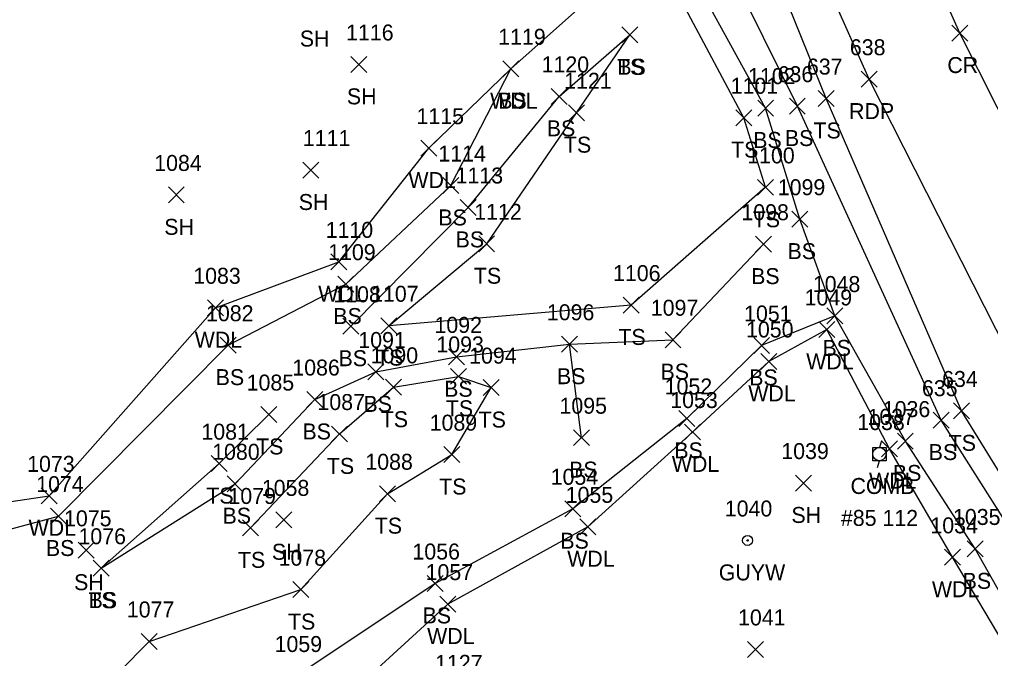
# Model space of a CAD drawing. Extents: x 1879695 to 1880991, y 836466 to 845172.
# Drawn here: x 1879765.9 to 1879887.6, y 844375.9 to 844455.9 of the extents above; entities that cross this region are included whole.
import ezdxf

# ---------------------------------------------------------------- set-up
doc = ezdxf.new("R2010")
doc.units = 0
for name, color, linetype in [('L_A', 7, 'Continuous'), ('L_I', 7, 'Continuous'), ('L_TIC', 7, 'Continuous'), ('LAWA', 7, 'Continuous'), ('LELB', 7, 'Continuous'), ('P_A', 7, 'Continuous'), ('P_I', 7, 'Continuous'), ('P_TIC', 7, 'Continuous'), ('PET', 7, 'Continuous'), ('PRC', 7, 'Continuous'), ('U_A', 7, 'Continuous'), ('U_C', 7, 'Continuous'), ('U_I', 7, 'Continuous'), ('UP', 7, 'Continuous'), ('UPGW', 7, 'Continuous')]:
    doc.layers.add(name, color=color, linetype=linetype)

msp = doc.modelspace()

# ---------------------------------------------------------------- linework, layer by layer
at = {"layer": 'L_TIC'}
for points in [[(1879841.38, 844452.99), (1879843.38, 844454.99)], [(1879843.38, 844452.99), (1879841.38, 844454.99)], [(1879841.38, 844452.99), (1879843.38, 844454.99)], [(1879843.38, 844452.99), (1879841.38, 844454.99)], [(1879807.45, 844449.29), (1879809.45, 844451.29)], [(1879809.45, 844449.29), (1879807.45, 844451.29)], [(1879826.46, 844448.75), (1879828.46, 844450.75)], [(1879828.46, 844448.75), (1879826.46, 844450.75)], [(1879826.46, 844448.75), (1879828.46, 844450.75)], [(1879828.46, 844448.75), (1879826.46, 844450.75)], [(1879832.54, 844445.29), (1879834.54, 844447.29)], [(1879834.54, 844445.29), (1879832.54, 844447.29)], [(1879865.98, 844445.02), (1879867.98, 844447.02)], [(1879867.98, 844445.02), (1879865.98, 844447.02)], [(1879834.72, 844443.24), (1879836.72, 844445.24)], [(1879836.72, 844443.24), (1879834.72, 844445.24)], [(1879858.4, 844443.83), (1879860.4, 844445.83)], [(1879860.4, 844443.83), (1879858.4, 844445.83)], [(1879862.37, 844444.07), (1879864.37, 844446.07)], [(1879864.37, 844444.07), (1879862.37, 844446.07)], [(1879855.66, 844442.62), (1879857.66, 844444.62)], [(1879857.66, 844442.62), (1879855.66, 844444.62)], [(1879816.22, 844438.81), (1879818.22, 844440.81)], [(1879818.22, 844438.81), (1879816.22, 844440.81)], [(1879801.41, 844436.06), (1879803.41, 844438.06)], [(1879803.41, 844436.06), (1879801.41, 844438.06)], [(1879818.96, 844434.13), (1879820.96, 844436.13)], [(1879820.96, 844434.13), (1879818.96, 844436.13)], [(1879858.38, 844433.9), (1879860.38, 844435.9)], [(1879860.38, 844433.9), (1879858.38, 844435.9)], [(1879858.38, 844433.9), (1879860.38, 844435.9)], [(1879860.38, 844433.9), (1879858.38, 844435.9)], [(1879784.57, 844432.95), (1879786.57, 844434.95)], [(1879786.57, 844432.95), (1879784.57, 844434.95)], [(1879821.12, 844431.38), (1879823.12, 844433.38)], [(1879823.12, 844431.38), (1879821.12, 844433.38)], [(1879862.7, 844429.91), (1879864.7, 844431.91)], [(1879864.7, 844429.91), (1879862.7, 844431.91)], [(1879823.45, 844426.83), (1879825.45, 844428.83)], [(1879825.45, 844426.83), (1879823.45, 844428.83)], [(1879858.13, 844426.78), (1879860.13, 844428.78)], [(1879860.13, 844426.78), (1879858.13, 844428.78)], [(1879804.93, 844424.57), (1879806.93, 844426.57)], [(1879806.93, 844424.57), (1879804.93, 844426.57)], [(1879805.8, 844421.78), (1879807.8, 844423.78)], [(1879807.8, 844421.78), (1879805.8, 844423.78)], [(1879789.46, 844418.82), (1879791.46, 844420.82)], [(1879791.46, 844418.82), (1879789.46, 844420.82)], [(1879841.54, 844419.16), (1879843.54, 844421.16)], [(1879843.54, 844419.16), (1879841.54, 844421.16)], [(1879867.08, 844417.79), (1879869.08, 844419.79)], [(1879869.08, 844417.79), (1879867.08, 844419.79)], [(1879867.08, 844417.79), (1879869.08, 844419.79)], [(1879869.08, 844417.79), (1879867.08, 844419.79)], [(1879806.45, 844416.5), (1879808.45, 844418.5)], [(1879808.45, 844416.5), (1879806.45, 844418.5)], [(1879811.18, 844416.57), (1879813.18, 844418.57)], [(1879813.18, 844416.57), (1879811.18, 844418.57)], [(1879866.06, 844416.11), (1879868.06, 844418.11)], [(1879868.06, 844416.11), (1879866.06, 844418.11)], [(1879791.06, 844414.13), (1879793.06, 844416.13)], [(1879793.06, 844414.13), (1879791.06, 844416.13)], [(1879833.82, 844414.25), (1879835.82, 844416.25)], [(1879835.82, 844414.25), (1879833.82, 844416.25)], [(1879833.82, 844414.25), (1879835.82, 844416.25)], [(1879835.82, 844414.25), (1879833.82, 844416.25)], [(1879846.79, 844414.82), (1879848.79, 844416.82)], [(1879848.79, 844414.82), (1879846.79, 844416.82)], [(1879857.9, 844414.1), (1879859.9, 844416.1)], [(1879859.9, 844414.1), (1879857.9, 844416.1)], [(1879819.68, 844412.67), (1879821.68, 844414.67)], [(1879821.68, 844412.67), (1879819.68, 844414.67)], [(1879858.8, 844412.1), (1879860.8, 844414.1)], [(1879860.8, 844412.1), (1879858.8, 844414.1)], [(1879809.57, 844410.78), (1879811.57, 844412.78)], [(1879811.57, 844410.78), (1879809.57, 844412.78)], [(1879819.92, 844410.23), (1879821.92, 844412.23)], [(1879821.92, 844410.23), (1879819.92, 844412.23)], [(1879811.77, 844408.86), (1879813.77, 844410.86)], [(1879813.77, 844408.86), (1879811.77, 844410.86)], [(1879824.03, 844408.82), (1879826.03, 844410.82)], [(1879826.03, 844408.82), (1879824.03, 844410.82)], [(1879824.03, 844408.82), (1879826.03, 844410.82)], [(1879826.03, 844408.82), (1879824.03, 844410.82)], [(1879801.93, 844407.33), (1879803.93, 844409.33)], [(1879803.93, 844407.33), (1879801.93, 844409.33)], [(1879796.16, 844405.45), (1879798.16, 844407.45)], [(1879798.16, 844405.45), (1879796.16, 844407.45)], [(1879882.92, 844405.9), (1879884.92, 844407.9)], [(1879884.92, 844405.9), (1879882.92, 844407.9)], [(1879848.52, 844404.96), (1879850.52, 844406.96)], [(1879850.52, 844404.96), (1879848.52, 844406.96)], [(1879880.39, 844404.75), (1879882.39, 844406.75)], [(1879882.39, 844404.75), (1879880.39, 844406.75)], [(1879805.02, 844403.01), (1879807.02, 844405.01)], [(1879807.02, 844403.01), (1879805.02, 844405.01)], [(1879849.22, 844403.26), (1879851.22, 844405.26)], [(1879851.22, 844403.26), (1879849.22, 844405.26)], [(1879835.34, 844402.55), (1879837.34, 844404.55)], [(1879837.34, 844402.55), (1879835.34, 844404.55)], [(1879875.9, 844402.13), (1879877.9, 844404.13)], [(1879877.9, 844402.13), (1879875.9, 844404.13)], [(1879819.09, 844400.43), (1879821.09, 844402.43)], [(1879821.09, 844400.43), (1879819.09, 844402.43)], [(1879873.93, 844401.15), (1879875.93, 844403.15)], [(1879875.93, 844401.15), (1879873.93, 844403.15)], [(1879789.92, 844399.3), (1879791.92, 844401.3)], [(1879791.92, 844399.3), (1879789.92, 844401.3)], [(1879791.92, 844396.78), (1879793.92, 844398.78)], [(1879793.92, 844396.78), (1879791.92, 844398.78)], [(1879863.14, 844396.87), (1879865.14, 844398.87)], [(1879865.14, 844396.87), (1879863.14, 844398.87)], [(1879811.02, 844395.53), (1879813.02, 844397.53)], [(1879813.02, 844395.53), (1879811.02, 844397.53)], [(1879768.65, 844395.27), (1879770.65, 844397.27)], [(1879770.65, 844395.27), (1879768.65, 844397.27)], [(1879834.24, 844393.65), (1879836.24, 844395.65)], [(1879836.24, 844393.65), (1879834.24, 844395.65)], [(1879769.79, 844392.73), (1879771.79, 844394.73)], [(1879771.79, 844392.73), (1879769.79, 844394.73)], [(1879798.05, 844392.26), (1879800.05, 844394.26)], [(1879800.05, 844392.26), (1879798.05, 844394.26)], [(1879793.88, 844391.25), (1879795.88, 844393.25)], [(1879795.88, 844391.25), (1879793.88, 844393.25)], [(1879836.13, 844391.39), (1879838.13, 844393.39)], [(1879838.13, 844391.39), (1879836.13, 844393.39)], [(1879773.27, 844388.45), (1879775.27, 844390.45)], [(1879775.27, 844388.45), (1879773.27, 844390.45)], [(1879884.64, 844388.62), (1879886.64, 844390.62)], [(1879886.64, 844388.62), (1879884.64, 844390.62)], [(1879881.81, 844387.57), (1879883.81, 844389.57)], [(1879883.81, 844387.57), (1879881.81, 844389.57)], [(1879775.14, 844386.2), (1879777.14, 844388.2)], [(1879777.14, 844386.2), (1879775.14, 844388.2)], [(1879775.14, 844386.2), (1879777.14, 844388.2)], [(1879777.14, 844386.2), (1879775.14, 844388.2)], [(1879800.15, 844383.52), (1879802.15, 844385.52)], [(1879802.15, 844383.52), (1879800.15, 844385.52)], [(1879816.98, 844384.29), (1879818.98, 844386.29)], [(1879818.98, 844384.29), (1879816.98, 844386.29)], [(1879818.57, 844381.71), (1879820.57, 844383.71)], [(1879820.57, 844381.71), (1879818.57, 844383.71)], [(1879781.15, 844377.04), (1879783.15, 844379.04)], [(1879783.15, 844377.04), (1879781.15, 844379.04)], [(1879857.14, 844376.04), (1879859.14, 844378.04)], [(1879859.14, 844376.04), (1879857.14, 844378.04)]]:
    msp.add_lwpolyline(points, dxfattribs=at)
at = {"layer": 'LAWA'}
for points in [[(1879751.37, 844393.55), (1879769.65, 844396.27), (1879790.46, 844419.82), (1879805.93, 844425.57), (1879817.22, 844439.81), (1879827.46, 844449.75), (1879840.76, 844461.61)], [(1879894.06, 844369.68), (1879882.81, 844388.57), (1879874.93, 844402.15), (1879867.06, 844417.11), (1879859.8, 844413.1), (1879850.22, 844404.26), (1879837.13, 844392.39), (1879819.57, 844382.71), (1879804.42, 844368.86)]]:
    msp.add_lwpolyline(points, dxfattribs=at)
at = {"layer": 'LELB'}
for points in [[(1880237.65, 844030.17), (1880225.55, 844045.25), (1880203.19, 844067.94), (1880175.04, 844095.38), (1880141.55, 844124.24), (1880111.59, 844152.12), (1880079.67, 844179.09), (1880044.89, 844208.16), (1880013.5, 844237.54), (1880003.34, 844247.82), (1879979.16, 844270.62), (1879948.51, 844300.87), (1879928.97, 844335.67), (1879901.59, 844373.87), (1879881.39, 844405.75), (1879863.37, 844445.07), (1879846.41, 844479.41), (1879833.35, 844517.23), (1879821, 844560.9), (1879811.24, 844600.26), (1879800.64, 844646.71), (1879794.2, 844680.16), (1879792.03, 844683.6), (1879789.08, 844683.63)], [(1880243.53, 844023.94), (1880226.64, 844046.28), (1880204.68, 844069.12), (1880177.19, 844097.39), (1880144.15, 844127.37), (1880114.34, 844154.46), (1880082.65, 844181.38), (1880047.53, 844211.78), (1880015.32, 844240.12), (1879982.29, 844271.84), (1879951.96, 844303.04), (1879930.28, 844336.91), (1879904.08, 844374.32), (1879883.92, 844406.9), (1879866.98, 844446.02), (1879852.23, 844482.49), (1879838.68, 844519.35), (1879826.86, 844562.48), (1879815.22, 844600.52)], [(1879859.38, 844434.9), (1879856.66, 844443.62), (1879845.03, 844465.48), (1879840.19, 844477.11)], [(1879868.08, 844418.79), (1879863.7, 844430.91), (1879859.4, 844444.83), (1879847.49, 844466.49)], [(1879807.45, 844417.5), (1879822.12, 844432.38), (1879833.54, 844446.29), (1879842.38, 844453.99)], [(1879859.38, 844434.9), (1879842.54, 844420.16), (1879812.18, 844417.57), (1879824.45, 844427.83), (1879835.72, 844444.24), (1879842.38, 844453.99)], [(1879753.64, 844389.12), (1879770.79, 844393.73), (1879792.06, 844415.13), (1879806.8, 844422.78), (1879819.96, 844435.13), (1879827.46, 844449.75)], [(1879836.34, 844403.55), (1879834.82, 844415.25), (1879847.79, 844415.82), (1879859.13, 844427.78)], [(1880002.51, 844242.73), (1879985.64, 844257.52), (1879965.17, 844278.62), (1879940.72, 844305.37), (1879925.82, 844326.46), (1879896.67, 844370.14), (1879885.64, 844389.62), (1879876.9, 844403.13), (1879868.08, 844418.79), (1879858.9, 844415.1), (1879849.52, 844405.96), (1879835.24, 844394.65), (1879817.98, 844385.29), (1879800.66, 844373.71), (1879774.59, 844370.4), (1879756.19, 844355.96), (1879741.66, 844350.26)], [(1879776.14, 844387.2), (1879792.92, 844397.78), (1879802.93, 844408.33), (1879810.57, 844411.78), (1879820.68, 844413.67), (1879834.82, 844415.25)], [(1879794.88, 844392.25), (1879806.02, 844404.01), (1879812.77, 844409.86), (1879820.92, 844411.23), (1879825.03, 844409.82)], [(1879774.59, 844370.4), (1879782.15, 844378.04), (1879801.15, 844384.52), (1879812.02, 844396.53), (1879820.09, 844401.43), (1879825.03, 844409.82)], [(1879776.14, 844387.2), (1879790.92, 844400.3), (1879797.16, 844406.45)]]:
    msp.add_lwpolyline(points, dxfattribs=at)
at = {"layer": 'P_TIC'}
for points in [[(1879882.72, 844453.21), (1879884.72, 844455.21)], [(1879884.72, 844453.21), (1879882.72, 844455.21)], [(1879871.36, 844447.44), (1879873.36, 844449.44)], [(1879873.36, 844447.44), (1879871.36, 844449.44)]]:
    msp.add_lwpolyline(points, dxfattribs=at)
at = {"layer": 'PET'}
msp.add_lwpolyline([(1880246.17, 844024.86), (1880229.35, 844048.54), (1880207.67, 844072.23), (1880179.65, 844099.99), (1880146.48, 844130.19), (1880116.3, 844156.76), (1880085.61, 844184.86), (1880050.42, 844215.32), (1880017.65, 844245.83), (1879986.99, 844277.13), (1879959.04, 844308.59), (1879934.2, 844340.79), (1879910.26, 844378.73), (1879891.14, 844411.43), (1879872.36, 844448.44), (1879856.33, 844484.43), (1879842.37, 844521.56), (1879829.6, 844563.28), (1879820.43, 844602.23)], dxfattribs=at)
at = {"layer": 'PRC'}
msp.add_lwpolyline([(1880256.85, 844032.04), (1880238.91, 844056.2), (1880216.7, 844080.65), (1880187.27, 844108.93), (1880154.23, 844138.82), (1880124.19, 844165.48), (1880092.74, 844193.41), (1880058.56, 844223.39), (1880025.99, 844253.92), (1879995.14, 844285.41), (1879968.79, 844316.24), (1879945.09, 844347.91), (1879920.67, 844385.19), (1879902.45, 844417.14), (1879883.72, 844454.21), (1879868.53, 844488.38), (1879854.47, 844526.01), (1879841.81, 844566.38), (1879832.13, 844605)], dxfattribs=at)
at = {"layer": 'UP'}
for p, q in [((1879873.9, 844403.17), (1879873.65, 844402.33)), ((1879872.81, 844400.67), (1879872.81, 844402.33)), ((1879872.81, 844402.33), (1879874.48, 844402.33)), ((1879873.65, 844401.5), (1879873.65, 844401.5)), ((1879874.48, 844402.33), (1879874.48, 844400.67)), ((1879874.48, 844400.67), (1879872.81, 844400.67)), ((1879873.4, 844399.83), (1879873.65, 844400.67))]:
    msp.add_line(p, q, dxfattribs=at)
msp.add_circle((1879873.65, 844401.5), 0.833, dxfattribs=at)
at = {"layer": 'UPGW'}
for radius in [0.625, 0.0833]:
    msp.add_circle((1879857.13, 844390.68), radius, dxfattribs=at)

# ---------------------------------------------------------------- texts
at = {"layer": 'L_A'}
for s, p in [('SH', (1879801.04, 844452.53)), ('TS', (1879840.78, 844448.99)), ('BS', (1879840.82, 844448.99)), ('SH', (1879806.94, 844445.29)), ('WDL', (1879824.88, 844444.75)), ('BS', (1879825.9, 844444.75)), ('BS', (1879831.98, 844441.29)), ('TS', (1879865.39, 844441.02)), ('BS', (1879857.84, 844439.83)), ('BS', (1879861.81, 844440.07)), ('TS', (1879834.13, 844439.24)), ('TS', (1879855.07, 844438.62)), ('WDL', (1879814.64, 844434.81)), ('SH', (1879800.9, 844432.06)), ('BS', (1879818.4, 844430.13)), ('TS', (1879857.79, 844429.9)), ('TS', (1879857.79, 844429.9)), ('SH', (1879784.06, 844428.95)), ('BS', (1879820.56, 844427.38)), ('BS', (1879862.14, 844425.91)), ('TS', (1879822.85, 844422.83)), ('BS', (1879857.58, 844422.78)), ('WDL', (1879803.35, 844420.57)), ('BS', (1879805.24, 844417.78)), ('TS', (1879840.95, 844415.16)), ('WDL', (1879787.87, 844414.82)), ('BS', (1879866.52, 844413.79)), ('BS', (1879866.52, 844413.79)), ('BS', (1879805.89, 844412.5)), ('TS', (1879810.59, 844412.57)), ('WDL', (1879864.48, 844412.11)), ('BS', (1879790.5, 844410.13)), ('BS', (1879833.26, 844410.25)), ('BS', (1879833.26, 844410.25)), ('BS', (1879846.23, 844410.82)), ('BS', (1879857.34, 844410.1)), ('BS', (1879819.12, 844408.67)), ('WDL', (1879857.22, 844408.1)), ('BS', (1879809.01, 844406.78)), ('TS', (1879819.33, 844406.23)), ('TS', (1879811.18, 844404.86)), ('TS', (1879823.44, 844404.82)), ('TS', (1879823.44, 844404.82)), ('BS', (1879801.37, 844403.33)), ('TS', (1879882.33, 844401.9)), ('TS', (1879795.57, 844401.45)), ('BS', (1879847.96, 844400.96)), ('BS', (1879879.83, 844400.75)), ('WDL', (1879847.64, 844399.26)), ('TS', (1879804.43, 844399.01)), ('BS', (1879834.78, 844398.55)), ('BS', (1879875.34, 844398.13)), ('WDL', (1879872.35, 844397.15)), ('TS', (1879818.5, 844396.43)), ('TS', (1879789.33, 844395.3)), ('BS', (1879791.36, 844392.78)), ('SH', (1879862.63, 844392.87)), ('WDL', (1879767.06, 844391.27)), ('TS', (1879810.43, 844391.53)), ('BS', (1879833.68, 844389.65)), ('BS', (1879769.23, 844388.73)), ('SH', (1879797.54, 844388.26)), ('TS', (1879793.29, 844387.25)), ('WDL', (1879834.54, 844387.39)), ('BS', (1879884.08, 844384.62)), ('SH', (1879772.76, 844384.45)), ('WDL', (1879880.23, 844383.57)), ('TS', (1879774.55, 844382.2)), ('BS', (1879774.58, 844382.2)), ('BS', (1879816.42, 844380.29)), ('TS', (1879799.56, 844379.52)), ('WDL', (1879816.99, 844377.71))]:
    msp.add_text(s, height=2, dxfattribs=at).set_placement(p)
at = {"layer": 'L_I'}
for s, p in [('1116', (1879806.84, 844453.29)), ('1119', (1879825.89, 844452.75)), ('1119', (1879825.89, 844452.75)), ('1120', (1879831.33, 844449.29)), ('637', (1879864.57, 844449.02)), ('1102', (1879857.19, 844447.83)), ('636', (1879860.9, 844448.07)), ('1121', (1879834.16, 844447.24)), ('1101', (1879855.02, 844446.62)), ('1115', (1879815.66, 844442.81)), ('1111', (1879801.42, 844440.06)), ('1114', (1879818.4, 844438.13)), ('1084', (1879782.8, 844436.95)), ('1100', (1879857.09, 844437.9)), ('1100', (1879857.09, 844437.9)), ('1113', (1879820.56, 844435.38)), ('1099', (1879860.92, 844433.91)), ('1112', (1879822.89, 844430.83)), ('1098', (1879856.36, 844430.78)), ('1110', (1879804.28, 844428.57)), ('1109', (1879804.59, 844425.78)), ('1083', (1879787.69, 844422.82)), ('1106', (1879840.28, 844423.16)), ('1048', (1879865.31, 844421.79)), ('1048', (1879865.31, 844421.79)), ('1108', (1879805.24, 844420.5)), ('1107', (1879809.97, 844420.57)), ('1049', (1879864.28, 844420.11)), ('1097', (1879845.01, 844418.82)), ('1082', (1879789.29, 844418.13)), ('1096', (1879831.99, 844418.25)), ('1096', (1879831.99, 844418.25)), ('1051', (1879856.7, 844418.1)), ('1092', (1879817.91, 844416.67)), ('1050', (1879856.94, 844416.1)), ('1091', (1879808.37, 844414.78)), ('1093', (1879818.15, 844414.23)), ('1090', (1879809.91, 844412.86)), ('1094', (1879822.26, 844412.82)), ('1094', (1879822.26, 844412.82)), ('1086', (1879800.1, 844411.33)), ('1085', (1879794.38, 844409.45)), ('1052', (1879846.75, 844408.96)), ('634', (1879881.51, 844409.9)), ('635', (1879878.98, 844408.75)), ('1087', (1879803.25, 844407.01)), ('1095', (1879833.57, 844406.55)), ('1053', (1879847.45, 844407.26)), ('1036', (1879874.07, 844406.13)), ('1089', (1879817.31, 844404.43)), ('1037', (1879872.16, 844405.15)), ('1081', (1879788.71, 844403.3)), ('1080', (1879790.06, 844400.78)), ('1039', (1879861.36, 844400.87)), ('1073', (1879766.88, 844399.27)), ('1088', (1879809.25, 844399.53)), ('1074', (1879768.02, 844396.73)), ('1054', (1879832.47, 844397.65)), ('1058', (1879796.28, 844396.26)), ('1079', (1879792.1, 844395.25)), ('1055', (1879834.35, 844395.39)), ('1075', (1879771.5, 844392.45)), ('1035', (1879882.87, 844392.62)), ('1034', (1879880.04, 844391.57)), ('1076', (1879773.31, 844390.2)), ('1076', (1879773.31, 844390.2)), ('1056', (1879815.15, 844388.29)), ('1078', (1879798.38, 844387.52)), ('1057', (1879816.8, 844385.71)), ('1077', (1879779.37, 844381.04)), ('1041', (1879855.94, 844380.04)), ('1059', (1879797.88, 844376.71))]:
    msp.add_text(s, height=2, dxfattribs=at).set_placement(p)
at = {"layer": 'P_A'}
for s, p in [('CR', (1879882.16, 844449.21)), ('RDP', (1879869.85, 844443.44))]:
    msp.add_text(s, height=2, dxfattribs=at).set_placement(p)
at = {"layer": 'P_I'}
msp.add_text('638', height=2, dxfattribs=at).set_placement((1879869.95, 844451.44))
at = {"layer": 'U_A'}
for s, p in [('COMB', (1879870.03, 844396.5)), ('GUYW', (1879853.53, 844385.68))]:
    msp.add_text(s, height=2, dxfattribs=at).set_placement(p)
at = {"layer": 'U_C'}
msp.add_text('#85 112', height=2, dxfattribs=at).set_placement((1879868.83, 844392.5))
at = {"layer": 'U_I'}
for s, p in [('1038', (1879870.88, 844404.5)), ('1040', (1879854.28, 844393.68)), ('1127', (1879817.99, 844374.35))]:
    msp.add_text(s, height=2, dxfattribs=at).set_placement(p)

doc.saveas('drawing.dxf')
